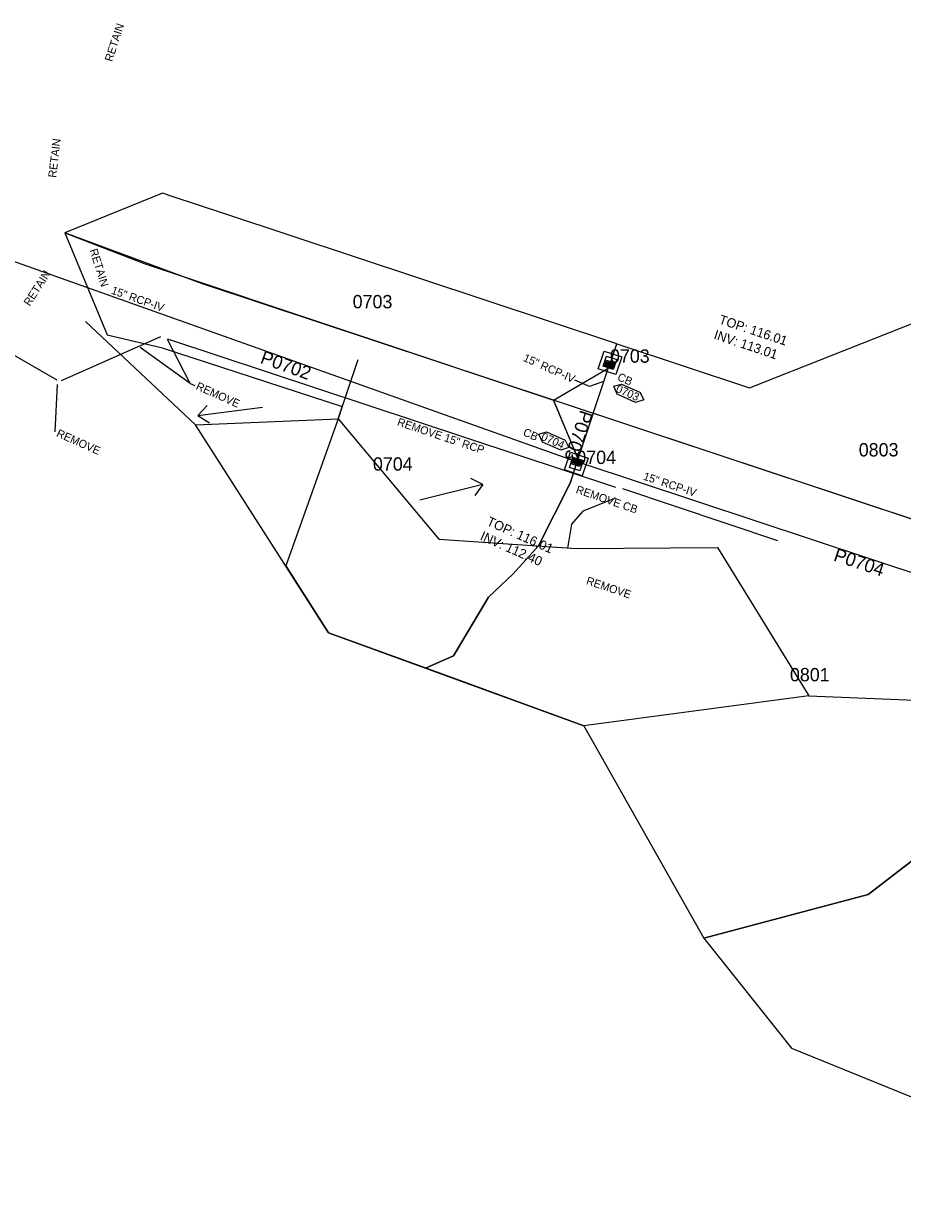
# Model space of a CAD drawing. Extents: x 2296558 to 2299313, y 599200 to 601383.
# Drawn here: x 2298630.1 to 2298959.5, y 599277.2 to 599713.5 of the extents above; entities that cross this region are included whole.
import ezdxf

# ---------------------------------------------------------------- set-up
doc = ezdxf.new("R2010")
doc.units = 0
for name, color, linetype in [('Prop Drainage Structure Box Number Symbol CELL', 7, 'Continuous'), ('Prop Drainage Structure Catch Basin Grate 840 03F CELL', 7, 'Continuous'), ('Prop Drainage Structure Catch Basin Grate 840 03F Label', 7, 'Continuous'), ('Prop Drainage Structure Catch Basin Grate 840 03G CELL', 7, 'Continuous'), ('Prop Drainage Structure Pipe RCP 15in Class IV', 7, 'Continuous'), ('Prop Drainage Structure Pipe RCP 15in Class IV Label', 7, 'Continuous'), ('Prop Drainage Structure Pipe Removal', 7, 'Continuous'), ('Prop Drainage Structure Plot Symbol 20 Scale', 7, 'Continuous'), ('Prop Drainage Structure Plot Symbol 50 Scale', 7, 'Continuous'), ('Prop Drainage Structure Removal Label', 7, 'Continuous'), ('Prop Drainage Structure Retain Label', 7, 'Continuous'), ('Prop Drainage Structure Tops and Inverts LABEL', 7, 'Continuous'), ('Prop Plan Preparation Watershed Post Construction', 7, 'Continuous'), ('Scratch_Level_1', 7, 'Continuous'), ('Scratch_Level_3', 7, 'Continuous'), ('Scratch_Level_5', 7, 'Continuous')]:
    doc.layers.add(name, color=color, linetype=linetype)

msp = doc.modelspace()

# ---------------------------------------------------------------- linework, layer by layer
at = {"layer": 'Prop Drainage Structure Box Number Symbol CELL'}
for points in [[(2298854.13, 599578.29), (2298861.03, 599575.21), (2298862.49, 599572.44), (2298859.45, 599571.44), (2298852.55, 599574.52), (2298851.23, 599577.46), (2298854.13, 599578.29)], [(2298826.11, 599560.35), (2298833.02, 599557.27), (2298834.48, 599554.49), (2298831.44, 599553.5), (2298824.53, 599556.58), (2298823.22, 599559.52), (2298826.11, 599560.35)]]:
    msp.add_lwpolyline(points, dxfattribs=at)
at = {"layer": 'Prop Drainage Structure Catch Basin Grate 840 03F CELL'}
for p, q in [((2298836.04, 599548.85), (2298836, 599548.91)), ((2298836.31, 599548.76), (2298836.09, 599549.17)), ((2298836.12, 599549.71), (2298836.12, 599549.71)), ((2298836.12, 599548.97), (2298836.15, 599548.91)), ((2298836.57, 599548.67), (2298836.18, 599549.44)), ((2298836.2, 599549.23), (2298836.42, 599548.82)), ((2298836.84, 599548.58), (2298836.27, 599549.7)), ((2298836.29, 599549.49), (2298836.69, 599548.73)), ((2298837.11, 599548.49), (2298836.35, 599549.96)), ((2298836.38, 599549.76), (2298836.95, 599548.64)), ((2298836.46, 599550.02), (2298837.22, 599548.55)), ((2298836.55, 599550.28), (2298837.32, 599548.8)), ((2298836.71, 599550.41), (2298837.41, 599549.06)), ((2298837.44, 599549.16), (2298836.86, 599550.26)), ((2298837.06, 599547.82), (2298837.06, 599547.82)), ((2298837.61, 599549.68), (2298837.4, 599550.09)), ((2298837.4, 599548.64), (2298837.49, 599548.46)), ((2298837.49, 599548.91), (2298837.76, 599548.37)), ((2298837.55, 599549.28), (2298837.55, 599549.28)), ((2298837.57, 599549.17), (2298838.03, 599548.28)), ((2298837.66, 599549.43), (2298838.3, 599548.19)), ((2298837.75, 599549.69), (2298838.57, 599548.1)), ((2298838.55, 599548.31), (2298837.78, 599549.79)), ((2298837.85, 599550.19), (2298837.85, 599550.19)), ((2298838.63, 599548.57), (2298837.94, 599549.91)), ((2298838.05, 599549.96), (2298838.74, 599548.62)), ((2298838.72, 599548.83), (2298838.21, 599549.82)), ((2298838.32, 599549.87), (2298838.83, 599548.89)), ((2298838.81, 599549.09), (2298838.48, 599549.73)), ((2298838.59, 599549.79), (2298838.92, 599549.15)), ((2298838.89, 599549.35), (2298838.75, 599549.64)), ((2298838.86, 599549.7), (2298839.01, 599549.41)), ((2298838.96, 599548.78), (2298838.96, 599548.78))]:
    msp.add_line(p, q, dxfattribs=at)
for points in [[(2298838.64, 599547.82), (2298835.79, 599548.77), (2298836.42, 599550.67), (2298839.27, 599549.72), (2298838.48, 599547.35), (2298835.64, 599548.29), (2298835.79, 599548.77)], [(2298835.81, 599548.77), (2298836.43, 599550.65), (2298839.26, 599549.71), (2298838.63, 599547.84), (2298835.81, 599548.77)], [(2298838.48, 599548.02), (2298835.96, 599548.85), (2298836.51, 599550.5), (2298839.1, 599549.64), (2298838.57, 599548.05)], [(2298837.32, 599548.8), (2298837.26, 599548.63), (2298836.44, 599550.22)], [(2298837.41, 599549.06), (2298837.35, 599548.89), (2298836.6, 599550.35)], [(2298836.98, 599550.32), (2298837.49, 599549.32), (2298837.44, 599549.16)], [(2298837.24, 599550.23), (2298837.58, 599549.58), (2298837.52, 599549.42), (2298837.13, 599550.17)], [(2298837.38, 599548.4), (2298837.34, 599548.48), (2298837.4, 599548.64)], [(2298837.67, 599549.85), (2298837.61, 599549.68), (2298837.4, 599550.09)], [(2298837.65, 599548.31), (2298837.43, 599548.74), (2298837.49, 599548.91)], [(2298837.51, 599550.14), (2298837.67, 599549.85), (2298837.61, 599549.68)], [(2298837.92, 599548.22), (2298837.52, 599549), (2298837.57, 599549.17)], [(2298838.19, 599548.13), (2298837.6, 599549.26), (2298837.66, 599549.43)], [(2298838.46, 599548.04), (2298837.69, 599549.53), (2298837.75, 599549.69)], [(2298837.78, 599549.79), (2298837.83, 599549.95), (2298838.66, 599548.36)]]:
    msp.add_lwpolyline(points, dxfattribs=at)
for centre, start, end in [((2298836.06, 599548.94), 27.3644, 207.3644), ((2298836.09, 599548.88), 207.3644, 27.3644), ((2298836.15, 599549.2), 27.3644, 207.3644), ((2298836.23, 599549.47), 27.3644, 207.3644), ((2298836.32, 599549.73), 27.3644, 207.3644), ((2298836.36, 599548.79), 207.3644, 27.3644), ((2298836.41, 599549.99), 27.3644, 207.3644), ((2298836.49, 599550.25), 27.3644, 207.3644), ((2298836.63, 599548.7), 207.3644, 27.3644), ((2298836.65, 599550.38), 27.3644, 207.3644), ((2298836.9, 599548.61), 207.3644, 27.3644), ((2298836.92, 599550.29), 27.3644, 207.3644), ((2298837.17, 599548.52), 207.3644, 27.3644), ((2298837.19, 599550.2), 27.3644, 207.3644), ((2298837.44, 599548.43), 207.3644, 27.3644), ((2298837.46, 599550.11), 27.3644, 207.3644), ((2298837.71, 599548.34), 207.3644, 27.3644), ((2298837.98, 599548.25), 207.3644, 27.3644), ((2298838, 599549.94), 27.3644, 207.3644), ((2298838.24, 599548.16), 207.3644, 27.3644), ((2298838.26, 599549.85), 27.3644, 207.3644), ((2298838.51, 599548.07), 207.3644, 27.3644), ((2298838.53, 599549.76), 27.3644, 207.3644), ((2298838.6, 599548.33), 207.3644, 27.3644), ((2298838.69, 599548.6), 207.3644, 27.3644), ((2298838.78, 599548.86), 207.3636, 27.3636), ((2298838.8, 599549.67), 27.3644, 207.3644), ((2298838.86, 599549.12), 207.3636, 27.3636), ((2298838.95, 599549.38), 207.3644, 27.3644)]:
    msp.add_arc(centre, 0.0625, start, end, dxfattribs=at)
at = {"layer": 'Prop Drainage Structure Catch Basin Grate 840 03G CELL'}
for p, q in [((2298849.15, 599586.27), (2298848.37, 599585.89)), ((2298848.88, 599586.36), (2298848.46, 599586.16)), ((2298848.49, 599586.53), (2298848.55, 599586.56)), ((2298848.61, 599586.45), (2298848.55, 599586.42)), ((2298849.99, 599586.77), (2298849.99, 599586.77)), ((2298848.08, 599585.78), (2298848.08, 599585.78)), ((2298849.61, 599585.84), (2298848.11, 599585.11)), ((2298849.53, 599585.57), (2298848.16, 599584.91)), ((2298849.69, 599586.09), (2298848.2, 599585.37)), ((2298849.42, 599586.18), (2298848.28, 599585.63)), ((2298849.44, 599585.31), (2298848.43, 599584.82)), ((2298849.35, 599585.05), (2298848.7, 599584.73)), ((2298849.26, 599584.79), (2298848.96, 599584.64)), ((2298849.2, 599584.41), (2298849.2, 599584.41)), ((2298849.45, 599584.57), (2298850.8, 599585.23)), ((2298849.5, 599585.31), (2298849.5, 599585.31)), ((2298850.86, 599585.12), (2298849.5, 599584.46)), ((2298849.72, 599584.49), (2298850.72, 599584.97)), ((2298850.77, 599584.86), (2298849.77, 599584.37)), ((2298849.99, 599584.4), (2298850.63, 599584.71)), ((2298850.68, 599584.6), (2298850.04, 599584.28)), ((2298850.26, 599584.31), (2298850.54, 599584.45)), ((2298850.6, 599584.33), (2298850.31, 599584.19)), ((2298850.93, 599584.87), (2298850.93, 599584.87))]:
    msp.add_line(p, q, dxfattribs=at)
for points in [[(2298848.41, 599586.77), (2298851.26, 599585.83), (2298850.63, 599583.93), (2298847.78, 599584.87), (2298848.57, 599587.25), (2298851.41, 599586.3), (2298851.26, 599585.83)], [(2298848.41, 599586.76), (2298851.24, 599585.82), (2298850.62, 599583.94), (2298847.79, 599584.88), (2298848.41, 599586.76)], [(2298850.54, 599584.1), (2298847.95, 599584.96), (2298848.49, 599586.6), (2298851.08, 599585.74), (2298850.54, 599584.1)], [(2298848.14, 599585.48), (2298849.63, 599586.2), (2298849.69, 599586.09)], [(2298848.23, 599585.74), (2298849.36, 599586.29), (2298849.42, 599586.18)], [(2298848.32, 599586.01), (2298849.09, 599586.38), (2298849.15, 599586.27)], [(2298848.4, 599586.27), (2298848.82, 599586.47), (2298848.88, 599586.36)], [(2298848.06, 599585.22), (2298849.67, 599586), (2298849.61, 599585.84)], [(2298848.1, 599585.02), (2298849.58, 599585.74), (2298849.53, 599585.57)], [(2298848.37, 599584.93), (2298849.49, 599585.48), (2298849.44, 599585.31)], [(2298848.64, 599584.84), (2298849.41, 599585.21), (2298849.35, 599585.05)], [(2298848.91, 599584.75), (2298849.32, 599584.95), (2298849.26, 599584.79)], [(2298850.95, 599585.38), (2298849.33, 599584.6), (2298849.39, 599584.77), (2298850.89, 599585.5)], [(2298851.03, 599585.65), (2298849.42, 599584.86), (2298849.48, 599585.03), (2298850.98, 599585.76)], [(2298850.76, 599585.73), (2298849.51, 599585.12), (2298849.56, 599585.29), (2298850.71, 599585.85)], [(2298850.49, 599585.82), (2298849.6, 599585.39), (2298849.65, 599585.55), (2298850.44, 599585.94)], [(2298850.22, 599585.91), (2298849.68, 599585.65), (2298849.74, 599585.82), (2298850.17, 599586.02)], [(2298849.95, 599586), (2298849.77, 599585.91), (2298849.82, 599586.08), (2298849.9, 599586.11)]]:
    msp.add_lwpolyline(points, dxfattribs=at)
for centre, start, end in [((2298848.43, 599586.21), 115.9098, 295.9098), ((2298848.52, 599586.47), 115.9098, 295.9098), ((2298848.58, 599586.5), 295.9098, 115.9098), ((2298848.08, 599585.16), 115.9098, 295.9098), ((2298848.13, 599584.96), 115.9098, 295.9098), ((2298848.17, 599585.42), 115.9098, 295.9098), ((2298848.26, 599585.69), 115.9098, 295.9098), ((2298848.34, 599585.95), 115.9098, 295.9098), ((2298848.4, 599584.88), 115.9098, 295.9098), ((2298848.67, 599584.79), 115.9098, 295.9098), ((2298848.94, 599584.7), 115.9098, 295.9098), ((2298849.48, 599584.52), 115.9098, 295.9098), ((2298849.74, 599584.43), 115.9098, 295.9098), ((2298849.93, 599586.06), 295.9098, 115.9098), ((2298850.01, 599584.34), 115.9098, 295.9098), ((2298850.2, 599585.97), 295.9098, 115.9098), ((2298850.28, 599584.25), 115.9098, 295.9098), ((2298850.46, 599585.88), 295.9098, 115.9098), ((2298850.57, 599584.39), 295.9098, 115.9098), ((2298850.66, 599584.65), 295.9098, 115.9098), ((2298850.73, 599585.79), 295.9098, 115.9098), ((2298850.74, 599584.91), 295.9098, 115.9098), ((2298850.83, 599585.18), 295.9098, 115.9098), ((2298850.92, 599585.44), 295.9098, 115.9098), ((2298851.01, 599585.7), 295.9098, 115.9098)]:
    msp.add_arc(centre, 0.0625, start, end, dxfattribs=at)
at = {"layer": 'Prop Drainage Structure Pipe RCP 15in Class IV'}
for p, q in [((2298604.31, 599632.25), (2298836.12, 599549.71)), ((2298849.2, 599584.41), (2298837.85, 599550.19)), ((2298838.96, 599548.78), (2299030.68, 599485.13))]:
    msp.add_line(p, q, dxfattribs=at)
at = {"layer": 'Prop Drainage Structure Pipe RCP 15in Class IV Label'}
for p, q in [((2298842.21, 599577.33), (2298836.69, 599579.8)), ((2298847.39, 599579.3), (2298842.21, 599577.33))]:
    msp.add_line(p, q, dxfattribs=at)
at = {"layer": 'Prop Drainage Structure Pipe Removal'}
for p, q in [((2298644.42, 599579.64), (2298681.67, 599596.1)), ((2298684.14, 599595.24), (2298851.96, 599539.7)), ((2298621.47, 599592.18), (2298642.74, 599579.93)), ((2298854.5, 599539.17), (2298912.6, 599519.71))]:
    msp.add_line(p, q, dxfattribs=at)
at = {"layer": 'Prop Drainage Structure Plot Symbol 20 Scale'}
for points in [[(2298851.09, 599583.73), (2298847.29, 599584.99), (2298848.55, 599588.79), (2298852.35, 599587.53)], [(2298835.96, 599550.86), (2298839.76, 599549.6), (2298838.5, 599545.81), (2298834.7, 599547.07)]]:
    msp.add_lwpolyline(points, close=True, dxfattribs=at)
at = {"layer": 'Prop Drainage Structure Plot Symbol 50 Scale'}
for points in [[(2298852.04, 599581.83), (2298845.39, 599584.04), (2298847.6, 599590.68), (2298854.24, 599588.48)], [(2298835.01, 599552.76), (2298841.65, 599550.55), (2298839.45, 599543.91), (2298832.81, 599546.12)]]:
    msp.add_lwpolyline(points, close=True, dxfattribs=at)
at = {"layer": 'Prop Drainage Structure Removal Label'}
for p, q in [((2298692.64, 599578.51), (2298684.16, 599595.02)), ((2298692.64, 599578.51), (2298673.92, 599591.99)), ((2298642.12, 599560.39), (2298642.99, 599578.18)), ((2298692.64, 599578.51), (2298694.41, 599577.73))]:
    msp.add_line(p, q, dxfattribs=at)
at = {"layer": 'Prop Plan Preparation Watershed Post Construction'}
for p, q in [((2298682.21, 599649.84), (2298645.63, 599634.98)), ((2298685.55, 599648.73), (2298682.21, 599649.84)), ((2298705.56, 599642.09), (2298685.55, 599648.73)), ((2298852.36, 599593.36), (2298705.56, 599642.09)), ((2298828.65, 599572.25), (2298696.9, 599615.99)), ((2299026.24, 599506.67), (2298828.65, 599572.25)), ((2298828.65, 599572.25), (2298837.86, 599550.23)), ((2298837.88, 599550.23), (2298828.65, 599572.25)), ((2298837.86, 599550.23), (2298834.87, 599541.22)), ((2298834.87, 599541.22), (2298837.88, 599550.23))]:
    msp.add_line(p, q, dxfattribs=at)
for points in [[(2298696.9, 599615.99), (2298645.63, 599634.98), (2298661.55, 599596.76), (2298681.73, 599592.05)], [(2298645.63, 599634.98), (2298675.4, 599623.47), (2298828.65, 599572.25)], [(2298852.36, 599593.36), (2298902.13, 599576.84), (2298965.28, 599601.86), (2298980.69, 599560.14), (2298974.85, 599552.7), (2299046.88, 599528.79)], [(2298681.73, 599592.05), (2298749.56, 599569.83), (2298748.03, 599565.3), (2298728.41, 599510.2), (2298744.47, 599485.12), (2298780.72, 599471.9), (2298780.72, 599471.9), (2298791.26, 599476.48), (2298804.4, 599498.43), (2298813.49, 599507.05), (2298823.02, 599517.66), (2298834.87, 599541.22)], [(2299025.75, 599506.83), (2298828.65, 599572.25), (2298849.36, 599584.35), (2298852.36, 599593.36)], [(2298828.65, 599572.25), (2298849.36, 599584.35), (2298852.36, 599593.36)], [(2298834.87, 599541.22), (2298823.02, 599517.66), (2298813.49, 599507.05), (2298804.4, 599498.43), (2298791.26, 599476.48), (2298780.72, 599471.9), (2298840.07, 599450.26), (2298884.99, 599370.73), (2298946.55, 599387.03), (2299043.68, 599461.69), (2299055.28, 599472.17), (2299051.16, 599490.96)]]:
    msp.add_lwpolyline(points, dxfattribs=at)
msp.add_lwpolyline([(2299043.68, 599461.69), (2298946.55, 599387.03), (2298884.99, 599370.73), (2298917.76, 599329.45), (2298985.68, 599301.81), (2299034.3, 599277.17), (2299099.24, 599471.26), (2299060.92, 599485.56), (2299058.03, 599486.63), (2299051.16, 599490.96), (2299055.28, 599472.17), (2299053.44, 599470.51)], close=True, dxfattribs=at)
at = {"layer": 'Scratch_Level_1'}
for p, q in [((2298748.03, 599565.3), (2298755.48, 599587.44)), ((2298695.54, 599566.5), (2298698.95, 599570.25)), ((2298695.54, 599566.5), (2298719.65, 599569.68)), ((2298695.54, 599566.5), (2298699.81, 599563.77)), ((2298802.22, 599540.63), (2298797.67, 599542.87)), ((2298802.22, 599540.63), (2298778.62, 599534.75)), ((2298802.22, 599540.63), (2298799.25, 599536.52))]:
    msp.add_line(p, q, dxfattribs=at)
for points in [[(2298902.13, 599576.84), (2298965.28, 599601.86), (2299021.46, 599638.7), (2299075.56, 599666.01)], [(2298653.47, 599601.76), (2298694.59, 599563.02), (2298748.03, 599565.3), (2298785.72, 599520.13), (2298837.27, 599516.71), (2298890.08, 599517.09), (2298924.3, 599461.48), (2298976.27, 599459.32), (2299024.41, 599445.64)], [(2298924.3, 599461.48), (2298840.07, 599450.26), (2298786.17, 599469.91), (2298744.47, 599485.12), (2298694.59, 599563.02)], [(2298851.95, 599535.55), (2298839.68, 599530.73), (2298835.48, 599525.81), (2298833.94, 599516.83)]]:
    msp.add_lwpolyline(points, dxfattribs=at)

# ---------------------------------------------------------------- texts
at = {"layer": 'Prop Drainage Structure Box Number Symbol CELL'}
for s, p in [('0703', (2298851.78, 599575.47)), ('0704', (2298823.79, 599557.52))]:
    msp.add_text(s, height=3, rotation=335.9431, dxfattribs=at).set_placement(p)
at = {"layer": 'Prop Drainage Structure Catch Basin Grate 840 03F Label'}
for p in [(2298852.35, 599579.9), (2298817.01, 599559.18)]:
    msp.add_text('CB', height=3, rotation=335.9431, dxfattribs=at).set_placement(p)
at = {"layer": 'Prop Drainage Structure Pipe RCP 15in Class IV Label'}
for rotation, p in [(340.4864, (2298662.81, 599612.22)), (335.9431, (2298817.07, 599587.06)), (341.6349, (2298862.05, 599542.53))]:
    msp.add_text('15" RCP-IV ', height=3, rotation=rotation, dxfattribs=at).set_placement(p)
at = {"layer": 'Prop Drainage Structure Removal Label'}
for s, rotation, p in [('REMOVE', 335.9431, (2298694.53, 599576.44)), ('REMOVE 15" RCP', 341.4828, (2298769.92, 599562.86)), ('REMOVE', 335.9431, (2298642.28, 599558.79)), ('REMOVE CB', 341.0033, (2298836.83, 599537.57)), ('REMOVE', 341.4828, (2298840.68, 599503.38))]:
    msp.add_text(s, height=3, rotation=rotation, dxfattribs=at).set_placement(p)
at = {"layer": 'Prop Drainage Structure Retain Label'}
for rotation, p in [(71.8574, (2298663.38, 599698.87)), (83.1046, (2298642.42, 599655.5)), (287.435, (2298654.93, 599628.48)), (57.2394, (2298632.56, 599607.26))]:
    msp.add_text('RETAIN', height=3, rotation=rotation, dxfattribs=at).set_placement(p)
at = {"layer": 'Prop Drainage Structure Tops and Inverts LABEL'}
for s, rotation, p in [('TOP: 116.01', 341.5664, (2298890.36, 599601.04)), ('INV: 113.01', 341.5664, (2298888.47, 599595.35)), ('TOP: 116.01', 335.9431, (2298803.35, 599525.57)), ('INV: 112.40', 335.9431, (2298800.91, 599520.09))]:
    msp.add_text(s, height=3.5, rotation=rotation, dxfattribs=at).set_placement(p)
at = {"layer": 'Scratch_Level_1'}
for s, p in [('0703', (2298753.47, 599606.68)), ('0803', (2298943, 599551.18)), ('0704', (2298761.07, 599545.85)), ('0801', (2298917.23, 599466.91))]:
    msp.add_text(s, height=5, dxfattribs=at).set_placement(p)
at = {"layer": 'Scratch_Level_3'}
for s, rotation, p in [('P0702', 340.4022, (2298718.54, 599586.27)), ('P0703', 251.6371, (2298838.78, 599568.88)), ('P0704', 341.6351, (2298933.24, 599512.21))]:
    msp.add_text(s, height=5, rotation=rotation, dxfattribs=at).set_placement(p)
at = {"layer": 'Scratch_Level_5'}
for s, p in [('0703', (2298849.83, 599586.3)), ('0704', (2298837.23, 599548.34))]:
    msp.add_text(s, height=5, dxfattribs=at).set_placement(p)

doc.saveas('drawing.dxf')
